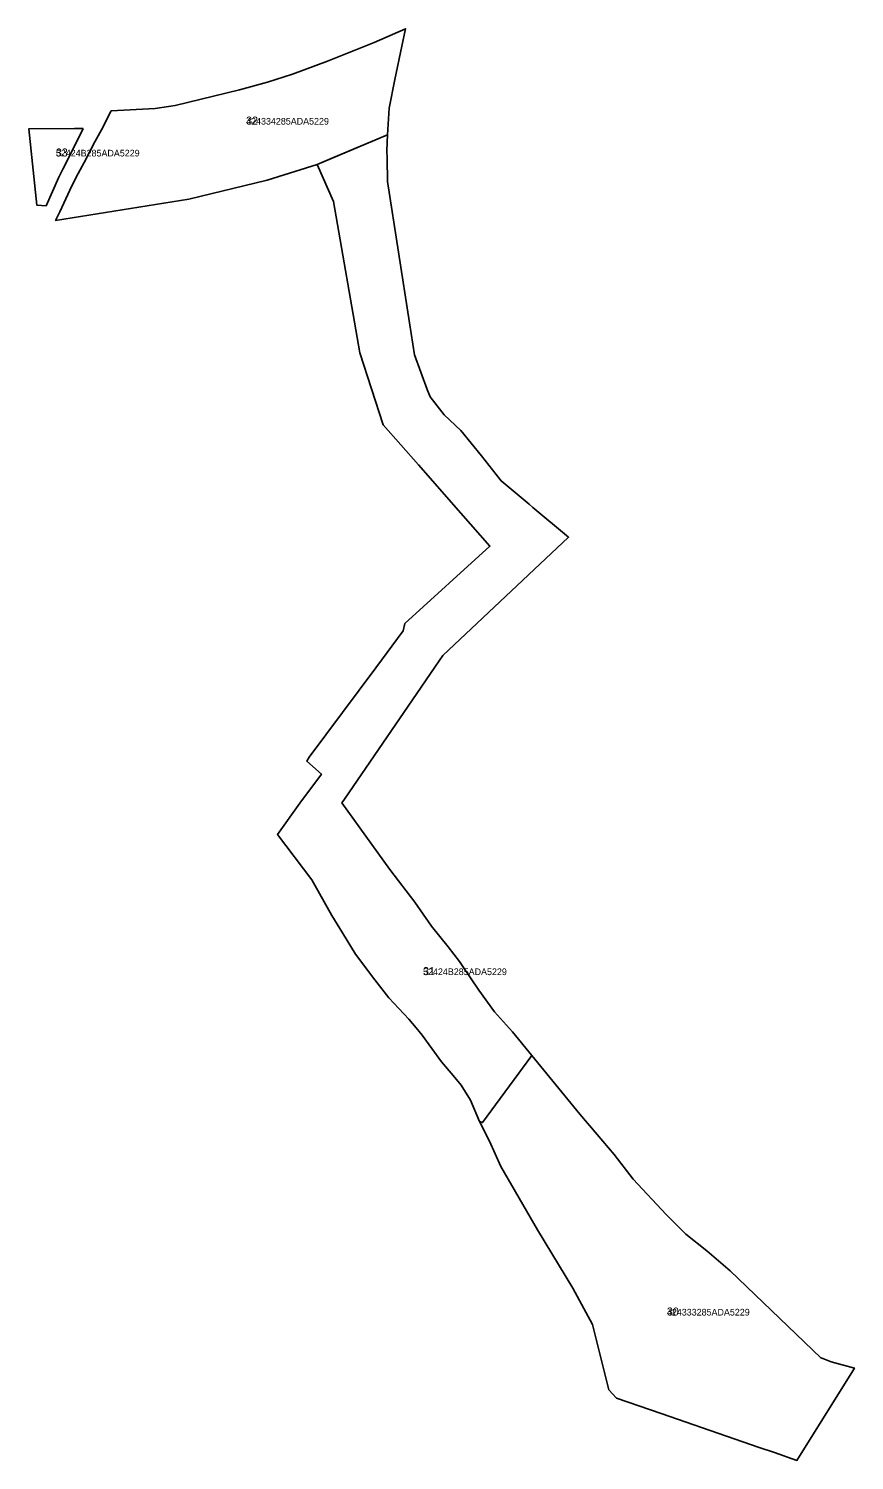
# Model space of a CAD drawing. Extents: x -540086 to -538022, y -1162553 to -1159940.
# Drawn here: x -539537 to -538917, y -1161013 to -1159940 of the extents above; entities that cross this region are included whole.
import ezdxf

# ---------------------------------------------------------------- set-up
doc = ezdxf.new("R2010")
doc.units = 0
doc.layers.add('96140023', color=7, linetype='Continuous')
doc.layers.add('ID_VPO', color=7, linetype='Continuous')

msp = doc.modelspace()

# ---------------------------------------------------------------- linework, layer by layer
at = {"layer": '96140023'}
for points in [[(-539504.1, -1160057.7), (-539499.3, -1160048.4), (-539494.9, -1160040.2), (-539486.8, -1160024.7), (-539482, -1160015.6), (-539474.6, -1160001.5), (-539441.6, -1159999.6), (-539426.7, -1159997.5), (-539378.3, -1159985.6), (-539357.3, -1159980), (-539338.6, -1159973.9), (-539312.3, -1159964.1), (-539277.4, -1159950.1), (-539253.8, -1159939.8), (-539256.5, -1159952.9), (-539261.8, -1159978), (-539266.2, -1159999.3), (-539267.3, -1160019.3), (-539320.1, -1160041.5), (-539357.5, -1160053.4), (-539416.5, -1160067.7), (-539516.3, -1160083.6), (-539513.2, -1160077)], [(-539495.7, -1160014.7), (-539497.7, -1160018.8), (-539510.8, -1160045.1), (-539513.8, -1160051.2), (-539523.4, -1160072.7), (-539530.4, -1160072.1), (-539536.5, -1160014.9), (-539502.2, -1160014.6)], [(-539225.8, -1160409.6), (-539228.5, -1160413.7), (-539248.6, -1160443), (-539299.6, -1160517.4), (-539301.5, -1160520.2), (-539265.6, -1160570.2), (-539246.9, -1160594.6), (-539234.4, -1160612.5), (-539221.8, -1160628.1), (-539213.3, -1160639.1), (-539211.3, -1160642.2), (-539198.8, -1160660.6), (-539187.2, -1160676.9), (-539184.9, -1160679.4), (-539173.7, -1160691.8), (-539159.2, -1160709.5), (-539196.1, -1160759.9), (-539198.3, -1160759.1), (-539205.2, -1160743), (-539212, -1160731.8), (-539218.1, -1160724.6), (-539226.9, -1160714.3), (-539241.3, -1160694.3), (-539245.9, -1160688.9), (-539251.4, -1160682.3), (-539266.3, -1160666.4), (-539278.5, -1160650.7), (-539283.7, -1160643.8), (-539291.4, -1160633.7), (-539301.2, -1160617.7), (-539309.2, -1160604.7), (-539324.2, -1160577.8), (-539349.8, -1160543.9), (-539333.2, -1160520.4), (-539316.9, -1160498.7), (-539327.9, -1160488.8), (-539326.2, -1160485.9), (-539276.2, -1160418.9), (-539255.5, -1160391.3), (-539254.3, -1160385.7), (-539190.5, -1160327.8), (-539212.4, -1160302.9), (-539244.2, -1160266.8), (-539270.6, -1160236.7), (-539288.1, -1160182.8), (-539307.8, -1160069.3), (-539320.1, -1160041.5), (-539307.8, -1160036.3), (-539267.3, -1160019.3), (-539267.8, -1160031.2), (-539267.7, -1160037), (-539267.4, -1160054.4), (-539250.9, -1160160.2), (-539247.2, -1160184.4), (-539237.6, -1160210.2), (-539235.4, -1160215.9), (-539224.8, -1160229.3), (-539212.3, -1160241.1), (-539196.9, -1160259.9), (-539183.2, -1160277.5), (-539182.2, -1160278.8), (-539161.2, -1160296.3), (-539158.4, -1160298.7), (-539131.6, -1160321.1)], [(-538988.5, -1161003.4), (-539062.1, -1160978), (-539095.6, -1160966.5), (-539101.3, -1160960.2), (-539113.6, -1160911.3), (-539128.4, -1160884.1), (-539154.8, -1160840.3), (-539182.3, -1160792.8), (-539190.9, -1160773.7), (-539198.3, -1160759.1), (-539196.1, -1160759.9), (-539159.2, -1160709.5), (-539123.1, -1160753.6), (-539110.2, -1160768.7), (-539097.3, -1160783.9), (-539083, -1160802.4), (-539058.4, -1160828.8), (-539056.1, -1160831.1), (-539043.6, -1160843.5), (-539027.9, -1160856), (-539010.4, -1160871), (-538942.3, -1160936.2), (-538940.9, -1160936.8), (-538934.5, -1160939.3), (-538917.2, -1160943.9), (-538960.3, -1161013.1), (-538977.1, -1161007.3)]]:
    msp.add_lwpolyline(points, close=True, dxfattribs=at)

# ---------------------------------------------------------------- texts
for s, rotation, p in [('424334285ADA5229', 360, (-539373.4, -1160011.7)), ('52424B285ADA5229', 0, (-539516.1, -1160035.6)), ('52424B285ADA5229', 0, (-539240.7, -1160649.3)), ('424333285ADA5229', 0, (-539057.8, -1160904.5))]:
    msp.add_text(s, height=5, rotation=rotation, dxfattribs=at).set_placement(p)
at = {"layer": 'ID_VPO'}
for s, rotation, p in [('32', 360, (-539373.4, -1160011.7)), ('33', 0, (-539516.1, -1160035.6)), ('31', 0, (-539240.7, -1160649.3)), ('30', 0, (-539057.8, -1160904.5))]:
    msp.add_text(s, height=6, rotation=rotation, dxfattribs=at).set_placement(p)

doc.saveas('drawing.dxf')
